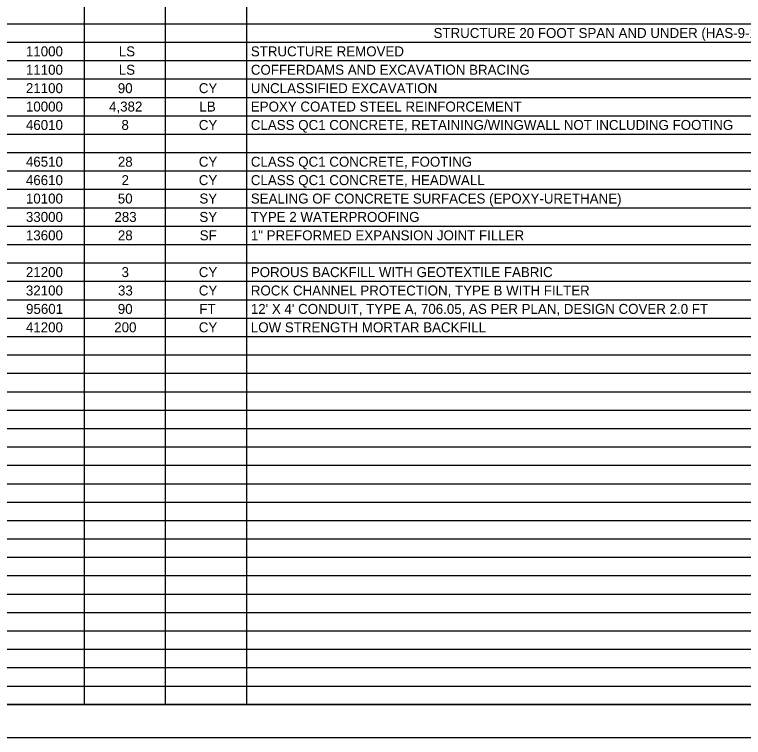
# Model space of a CAD drawing. Extents: x 0 to 1700, y 0 to 1100.
# Drawn here: x 849 to 1403, y 0 to 550 of the extents above; entities that cross this region are included whole.
import ezdxf

# ---------------------------------------------------------------- set-up
doc = ezdxf.new("R2010")
doc.units = 0
for name, color, linetype in [('SH_Border', 7, 'Continuous'), ('SH_Cut_Line', 7, 'Continuous'), ('SH_Text', 7, 'Continuous')]:
    doc.layers.add(name, color=color, linetype=linetype)

msp = doc.modelspace()

# ---------------------------------------------------------------- linework, layer by layer
at = {"layer": 'SH_Border'}
msp.add_lwpolyline([(75, 1075), (1675, 1075), (1675, 25), (75, 25)], close=True, dxfattribs=at)
at = {"layer": 'SH_Cut_Line'}
msp.add_lwpolyline([(0, 0), (1700, 0), (1700, 1100), (0, 1100)], close=True, dxfattribs=at)
at = {"layer": 'SH_Text'}
for p, q in [((901.73, 1075), (901.73, 25.12)), ((963.49, 1075), (963.49, 25.12)), ((1025.24, 1075), (1025.24, 25.12)), ((75, 543.06), (1600, 543.06)), ((75, 529.06), (1600, 529.06)), ((75, 515.06), (1600, 515.06)), ((75, 501.07), (1600, 501.07)), ((75, 487.07), (1600, 487.07)), ((75, 473.07), (1600, 473.07)), ((75, 459.07), (1600, 459.07)), ((75, 445.07), (1600, 445.07)), ((75, 431.07), (1600, 431.07)), ((75, 417.08), (1600, 417.08)), ((75, 403.08), (1600, 403.08)), ((75, 389.08), (1600, 389.08)), ((75, 375.08), (1600, 375.08)), ((75, 361.08), (1600, 361.08)), ((75, 347.08), (1600, 347.08)), ((75, 333.09), (1600, 333.09)), ((75, 319.09), (1600, 319.09)), ((75, 305.09), (1600, 305.09)), ((75, 291.09), (1600, 291.09)), ((75, 277.09), (1600, 277.09)), ((75, 263.09), (1600, 263.09)), ((75, 249.1), (1600, 249.1)), ((75, 235.1), (1600, 235.1)), ((75, 221.1), (1600, 221.1)), ((75, 207.1), (1600, 207.1)), ((75, 193.1), (1600, 193.1)), ((75, 179.1), (1600, 179.1)), ((75, 165.11), (1600, 165.11)), ((75, 151.11), (1600, 151.11)), ((75, 137.11), (1600, 137.11)), ((75, 123.11), (1600, 123.11)), ((75, 109.11), (1600, 109.11)), ((75, 95.11), (1600, 95.11)), ((75, 81.12), (1600, 81.12)), ((75, 67.12), (1600, 67.12)), ((75, 53.12), (1600, 53.12)), ((75, 39.12), (1600, 39.12)), ((75, 25.12), (1600, 25.12))]:
    msp.add_line(p, q, dxfattribs=at)

# ---------------------------------------------------------------- texts
for s, height, p in [('STRUCTURE 20 FOOT SPAN AND UNDER (HAS-9-17.04)', 7.5756, (1167.54, 532.27)), ('11000', 7.576, (857.43, 518.28)), ('LS', 7.576, (928.08, 518.28)), ('STRUCTURE REMOVED', 7.5756, (1028.54, 518.28)), ('11100', 7.576, (857.43, 504.28)), ('LS', 7.576, (928.08, 504.28)), ('COFFERDAMS AND EXCAVATION BRACING', 7.5756, (1028.54, 504.28)), ('21100', 7.576, (857.43, 490.28)), ('90', 7.576, (927.35, 490.28)), ('CY', 7.576, (988.96, 490.28)), ('UNCLASSIFIED EXCAVATION', 7.5756, (1028.54, 490.28)), ('10000', 7.576, (857.43, 476.28)), ('4,382', 7.576, (920.68, 476.28)), ('LB', 7.576, (989.42, 476.28)), ('EPOXY COATED STEEL REINFORCEMENT', 7.5756, (1028.54, 476.28)), ('46010', 7.576, (857.43, 462.28)), ('8', 7.58, (930.11, 462.28)), ('CY', 7.576, (988.96, 462.28)), ('CLASS QC1 CONCRETE, RETAINING/WINGWALL NOT INCLUDING FOOTING', 7.5756, (1028.54, 462.28)), ('46510', 7.576, (857.43, 434.29)), ('28', 7.576, (927.39, 434.29)), ('CY', 7.576, (988.96, 434.29)), ('CLASS QC1 CONCRETE, FOOTING', 7.5756, (1028.54, 434.29)), ('46610', 7.576, (857.43, 420.29)), ('2', 7.58, (930.18, 420.29)), ('CY', 7.576, (988.96, 420.29)), ('CLASS QC1 CONCRETE, HEADWALL', 7.5756, (1028.54, 420.29)), ('10100', 7.576, (857.43, 406.29)), ('50', 7.576, (927.35, 406.29)), ('SY', 7.576, (989.41, 406.29)), ('SEALING OF CONCRETE SURFACES (EPOXY-URETHANE)', 7.5756, (1028.54, 406.29)), ('33000', 7.576, (857.43, 392.29)), ('283', 7.576, (924.77, 392.29)), ('SY', 7.576, (989.41, 392.29)), ('TYPE 2 WATERPROOFING', 7.5756, (1028.54, 392.29)), ('13600', 7.576, (857.43, 378.29)), ('28', 7.576, (927.39, 378.29)), ('SF', 7.576, (989.66, 378.29)), ('1" PREFORMED EXPANSION JOINT FILLER', 7.5756, (1028.54, 378.29)), ('21200', 7.576, (857.43, 350.3)), ('3', 7.58, (930.21, 350.3)), ('CY', 7.576, (988.96, 350.3)), ('POROUS BACKFILL WITH GEOTEXTILE FABRIC', 7.5756, (1028.54, 350.3)), ('32100', 7.576, (857.43, 336.3)), ('33', 7.576, (927.49, 336.3)), ('CY', 7.576, (988.96, 336.3)), ('ROCK CHANNEL PROTECTION, TYPE B WITH FILTER', 7.5756, (1028.54, 336.3)), ('95601', 7.576, (857.54, 322.3)), ('90', 7.576, (927.35, 322.3)), ('FT', 7.576, (989.32, 322.3)), ("12' X 4' CONDUIT, TYPE A, 706.05, AS PER PLAN, DESIGN COVER 2.0 FT", 7.5756, (1028.54, 322.3)), ('41200', 7.576, (857.43, 308.3)), ('200', 7.576, (924.63, 308.3)), ('CY', 7.576, (988.96, 308.3)), ('LOW STRENGTH MORTAR BACKFILL', 7.5756, (1028.54, 308.3))]:
    msp.add_text(s, height=height, dxfattribs=at).set_placement(p)

doc.saveas('drawing.dxf')
